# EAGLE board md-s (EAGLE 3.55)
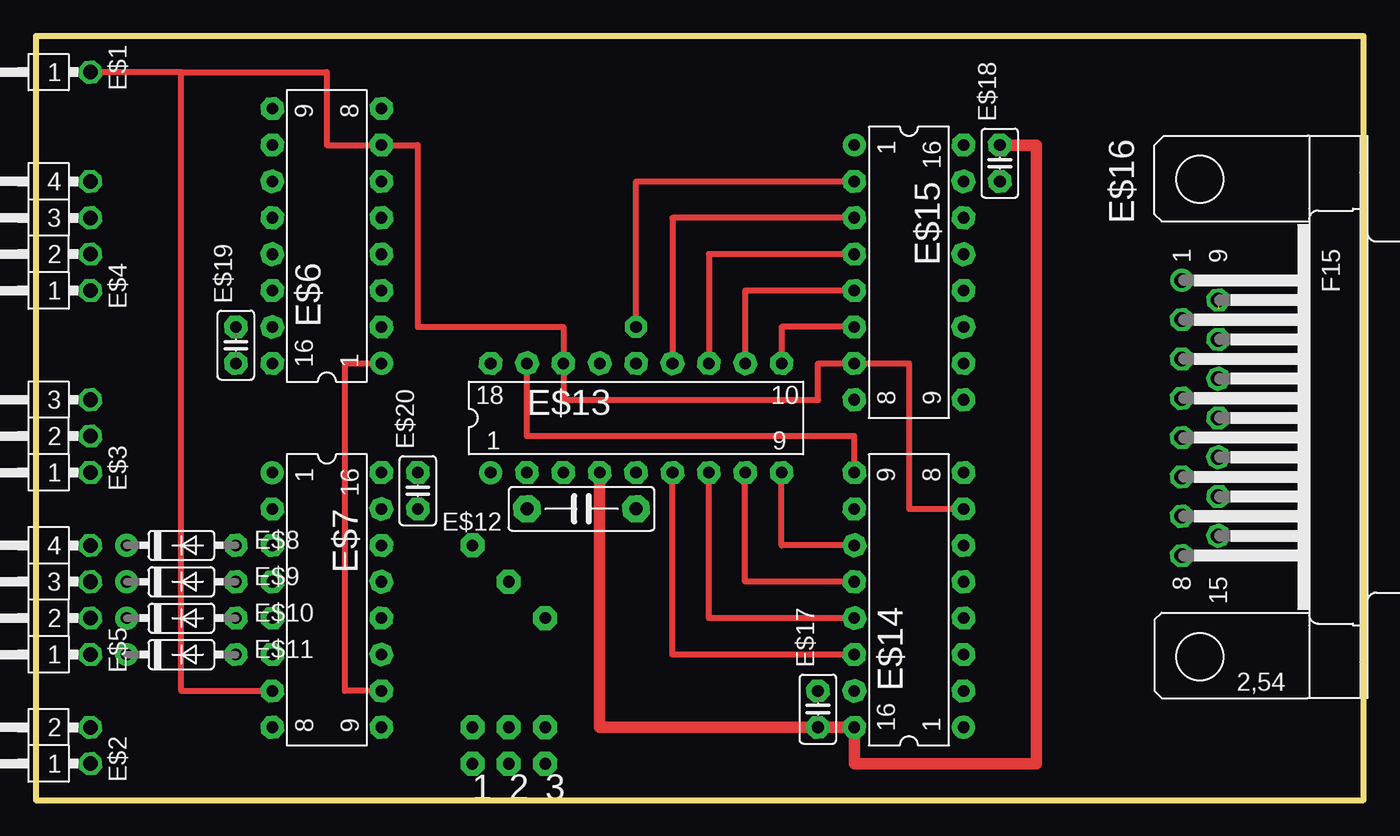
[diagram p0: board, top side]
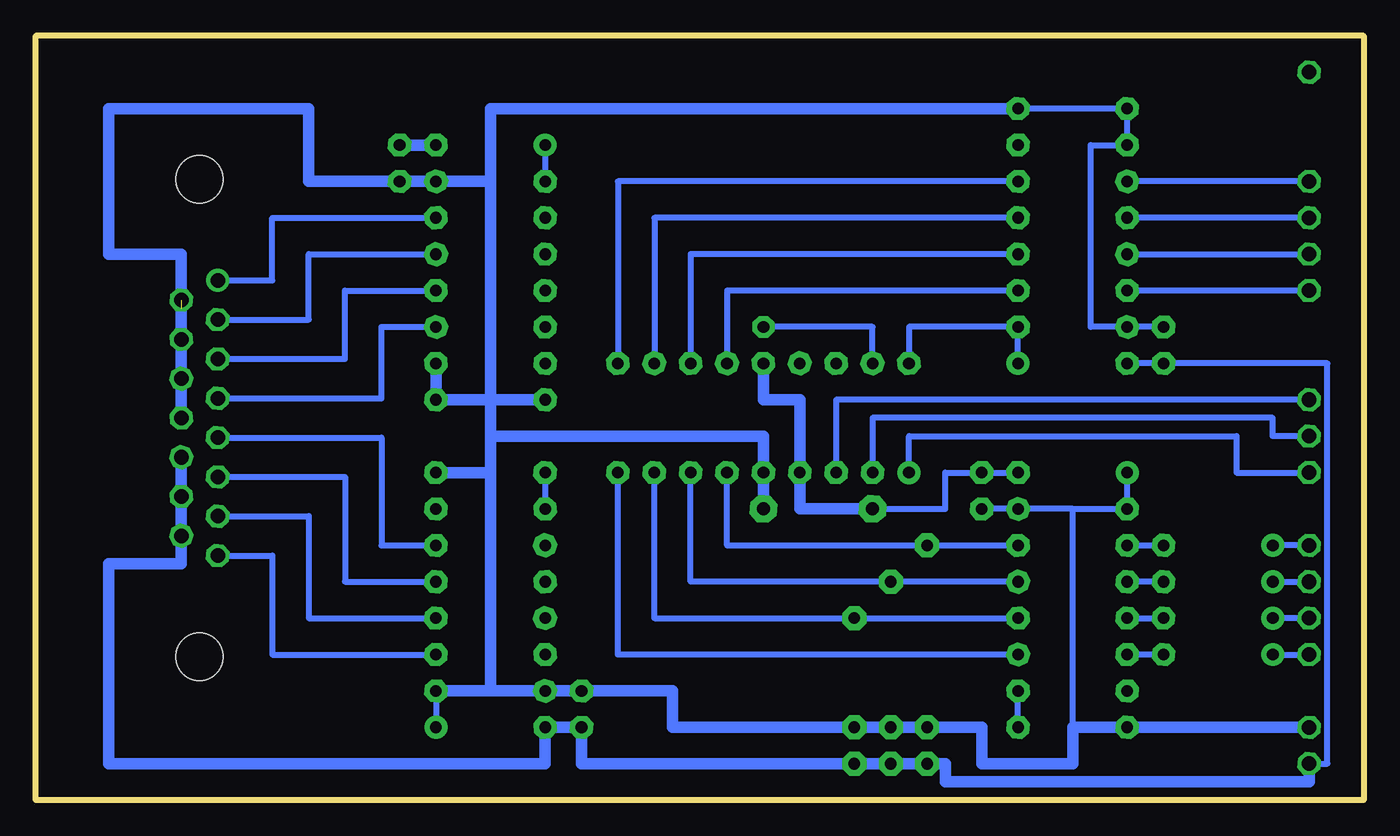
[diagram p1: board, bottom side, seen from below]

Size 92.71 x 53.34 mm. Coordinates in mm from the lower left corner, seen from the top.
Outline: 0,53.34 92.71,53.34 92.71,0 0,0 0,53.34
Copper layers used: Top, Bottom

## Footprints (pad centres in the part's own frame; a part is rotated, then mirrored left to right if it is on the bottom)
01-1W = drill 1.016 pad 1.6 octagon:  0,0
02-1W = drill 1.016 pad 1.6 octagon:  2.54,0;  0,0
03-1W = drill 1.016 pad 1.6 octagon:  5.08,0;  2.54,0;  0,0
04-1W = drill 1.016 pad 1.6 octagon:  7.62,0;  5.08,0;  2.54,0;  0,0
L16 = drill 0.813 pad 1.6 round:  -8.89,-3.81 | drill 0.813 pad 1.6 octagon:  -6.35,-3.81;  -3.81,-3.81;  -1.27,-3.81;  1.27,-3.81;  3.81,-3.81;  6.35,-3.81;  8.89,-3.81;  8.89,3.81;  6.35,3.81;  3.81,3.81;  1.27,3.81;  -1.27,3.81;  -3.81,3.81;  -6.35,3.81;  -8.89,3.81
35-7 = drill 0.813 pad 1.6 round:  -3.81,0 | drill 0.813 pad 1.6 octagon:  3.81,0
,5B3 = drill 0.914 pad 1.905 octagon:  -3.81,0;  3.81,0
L18 = drill 0.813 pad 1.6 round:  -10.16,-3.81 | drill 0.813 pad 1.6 octagon:  -7.62,-3.81;  -5.08,-3.81;  -2.54,-3.81;  0,-3.81;  2.54,-3.81;  5.08,-3.81;  7.62,-3.81;  10.16,-3.81;  10.16,3.81;  7.62,3.81;  5.08,3.81;  2.54,3.81;  0,3.81;  -2.54,3.81;  -5.08,3.81;  -7.62,3.81;  -10.16,3.81
5H = drill 1.016 pad 1.6 round:  -9.601,-1.27 | drill 1.016 pad 1.6 octagon:  -6.858,-1.27;  -4.115,-1.27;  -1.372,-1.27;  1.372,-1.27;  4.115,-1.27;  6.858,-1.27;  9.601,-1.27;  -8.23,1.27;  -5.486,1.27;  -2.743,1.27;  0,1.27;  2.743,1.27;  5.486,1.27;  8.23,1.27 | hole 3.302: -16.662,0; 16.662,0
,5-2 = drill 0.813 pad 1.6 octagon:  -1.27,0;  1.27,0

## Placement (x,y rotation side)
E$1  [01-1W]  3.81,50.8 90 top
E$2  [02-1W]  3.81,2.54 90 top
E$3  [03-1W]  3.81,22.86 90 top
E$4  [04-1W]  3.81,35.56 90 top
E$5  [04-1W]  3.81,10.16 90 top
E$6  74HC173  [L16]  20.32,39.37 90 top
E$7  74HC173  [L16]  20.32,13.97 270 top
E$8  1N4148  [35-7]  10.16,17.78 0 top
E$9  1N4148  [35-7]  10.16,15.24 0 top
E$10  1N4148  [35-7]  10.16,12.7 0 top
E$11  1N4148  [35-7]  10.16,10.16 0 top
E$12  0.1  [,5B3]  38.1,20.32 180 top
E$13  PIC16F84/10MHz  [L18]  41.91,26.67 0 top
E$14  74HC173  [L16]  60.96,13.97 90 top
E$15  74HC173  [L16]  60.96,36.83 270 top
E$16  SUB-D 15pin F  [5H]  81.28,26.67 270 top
E$17  0.1  [,5-2]  54.61,6.35 90 top
E$18  0.1  [,5-2]  67.31,44.45 90 top
E$19  0.1  [,5-2]  13.97,31.75 90 top
E$20  0.1  [,5-2]  26.67,21.59 90 top

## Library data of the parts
E$1-E$5 = con-lstb
E$6 E$7 E$14 E$15 = 74xx
E$8-E$11 = diode
E$12 E$17-E$20 = cap
E$13 = pic
E$16 = subd

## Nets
S$1: E$4. E$6.
S$2: E$4. E$6.
S$3: E$4. E$6.
S$4: E$4. E$6.
S$5: E$3. E$13.
S$6: E$3. E$13.
S$7: E$3. E$13.
S$8: E$7. E$11.
S$9: E$5. E$8.
S$10: E$5. E$9.
S$11: E$5. E$10.
S$12: E$5. E$11.
S$13: E$7. E$10.
S$14: E$7. E$9.
S$15: E$7. E$8.
S$16: E$6. E$7. E$13.
S$17: E$2. E$6. E$7. E$12. E$13. E$14. E$15. E$16. E$17. E$18. E$19. E$20.
S$18: E$7. E$13. E$14.
S$19: E$7. E$13. E$14.
S$20: E$7. E$13. E$14.
S$21: E$7. E$13. E$14.
S$22: E$2. E$6. E$7. E$12. E$13. E$14. E$15. E$16. E$17. E$18. E$19. E$20.
S$23: E$1. E$6. E$7. E$13. E$14. E$15.
S$25: E$13. E$14. E$15.
S$26: E$6. E$13. E$15.
S$27: E$6. E$13. E$15.
S$28: E$6. E$13. E$15.
S$29: E$6. E$13. E$15.
S$32: E$14. E$16.
S$33: E$14. E$16.
S$34: E$14. E$16.
S$35: E$14. E$16.
S$36: E$15. E$16.
S$37: E$15. E$16.
S$38: E$15. E$16.
S$39: E$15. E$16.

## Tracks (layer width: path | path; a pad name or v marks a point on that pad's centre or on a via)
S$1
  Bottom 0.406: 3.81,43.18 16.51,43.18
S$2
  Bottom 0.406: 3.81,40.64 16.51,40.64
S$3
  Bottom 0.406: 16.51,38.1 3.81,38.1
S$4
  Bottom 0.406: E$4. 16.51,35.56
S$5
  Bottom 0.406: 3.81,27.94 36.83,27.94 36.83,22.86
S$6
  Bottom 0.406: 3.81,25.4 6.35,25.4 6.35,26.67 34.29,26.67 34.29,22.86
S$7
  Bottom 0.406: 31.75,22.86 31.75,25.4 8.89,25.4 8.89,22.86 E$3.
S$8
  Bottom 0.406: E$11. 16.51,10.16
S$9
  Bottom 0.406: 3.81,17.78 6.35,17.78
S$10
  Bottom 0.406: 6.35,15.24 3.81,15.24
S$11
  Bottom 0.406: 3.81,12.7 6.35,12.7
S$12
  Bottom 0.406: 6.35,10.16 E$5.
S$13
  Bottom 0.406: 16.51,12.7 E$10.
S$14
  Bottom 0.406: E$9. 16.51,15.24
S$15
  Bottom 0.406: 16.51,17.78 E$8.
S$16
  Top 0.406: 24.13,7.62 21.59,7.62 21.59,30.48 24.13,30.48
  Bottom 0.406: 24.13,5.08 24.13,7.62 | 24.13,30.48 24.13,33.02 31.75,33.02 E$13.
S$17  (via drill 0.81 pad 1.68)  (1 unrouted)
  Bottom 0.406: 64.77,7.62 64.77,5.08 | 24.13,48.26 16.51,48.26 16.51,45.72 19.05,45.72 19.05,33.02 16.51,33.02 E$19. | 26.67,20.32 24.13,20.32 20.32,20.32 | 16.51,22.86 16.51,20.32 20.32,20.32 | 20.32,5.08 20.32,20.32
  Bottom 0.813: 82.55,26.67 82.55,29.41 82.55,32.16 82.55,34.29 | 82.55,34.9 82.55,38.1 87.63,38.1 87.63,48.26 73.66,48.26 73.66,43.18 67.31,43.18 64.77,43.18 60.96,43.18 | 41.91,20.32 41.91,22.86 41.91,25.4 60.96,25.4 | 60.96,7.62 64.77,7.62 | 60.96,7.62 57.15,7.62 E$17. 48.26,7.62 48.26,5.08 v35.56,5.08 v33.02,5.08 v30.48,5.08 26.67,5.08 26.67,2.54 20.32,2.54 20.32,5.08 16.51,5.08 3.81,5.08 | 60.96,22.86 64.77,22.86 | 60.96,22.86 60.96,7.62 | 60.96,25.4 60.96,22.86 | 64.77,30.48 64.77,27.94 60.96,27.94 | 60.96,27.94 57.15,27.94 | 60.96,27.94 60.96,25.4 | 60.96,43.18 60.96,27.94 | 60.96,43.18 60.96,48.26 24.13,48.26
S$18
  Top 0.406: 57.15,17.78 52.07,17.78 52.07,22.86
  Bottom 0.406: 52.07,22.86 52.07,10.16 24.13,10.16
S$19  (via drill 0.81 pad 1.68)
  Top 0.406: 57.15,15.24 49.53,15.24 49.53,22.86
  Bottom 0.406: 49.53,22.86 49.53,12.7 v35.56,12.7 24.13,12.7
S$20  (via drill 0.81 pad 1.68)
  Top 0.406: 57.15,12.7 46.99,12.7 46.99,22.86
  Bottom 0.406: 46.99,22.86 46.99,15.24 v33.02,15.24 24.13,15.24
S$21  (via drill 0.81 pad 1.68)
  Top 0.406: 57.15,10.16 44.45,10.16 44.45,22.86
  Bottom 0.406: 44.45,22.86 44.45,17.78 v30.48,17.78 24.13,17.78
S$22  (via drill 0.81 pad 1.68)
  Top 0.813: E$18. 69.85,45.72 69.85,2.54 57.15,2.54 E$14. 54.61,5.08 39.37,5.08 39.37,22.86
  Bottom 0.406: E$7. E$20. 29.21,22.86 29.21,20.32 E$12. | E$6. 13.97,30.48 2.54,30.48 2.54,2.54 E$2.
  Bottom 0.813: 82.55,21.59 82.55,23.93 | 82.55,21.59 82.55,21.18 | 82.55,21.59 E$16. 82.55,16.51 87.63,16.51 87.63,2.54 57.15,2.54 E$14. 54.61,5.08 54.61,2.54 v35.56,2.54 v33.02,2.54 v30.48,2.54 29.21,2.54 29.21,1.27 3.81,1.27 E$2. | E$18. E$15. | 41.91,30.48 41.91,27.94 39.37,27.94 39.37,22.86 39.37,20.32 E$12.
S$23
  Top 0.406: 10.16,50.8 E$1. | 10.16,50.8 20.32,50.8 20.32,45.72 24.13,45.72 26.67,45.72 26.67,33.02 36.83,33.02 36.83,30.48 36.83,27.94 54.61,27.94 54.61,30.48 57.15,30.48 60.96,30.48 60.96,20.32 64.77,20.32 | 16.51,7.62 10.16,7.62 10.16,50.8
S$25  (via drill 0.81 pad 1.52)
  Top 0.406: v41.91,33.02 41.91,43.18 57.15,43.18 | 57.15,22.86 57.15,25.4 34.29,25.4 34.29,30.48
  Bottom 0.406: 34.29,30.48 34.29,33.02 v41.91,33.02 | 57.15,45.72 57.15,43.18 | 57.15,22.86 57.15,20.32
S$26
  Top 0.406: 57.15,40.64 44.45,40.64 44.45,30.48
  Bottom 0.406: 24.13,35.56 44.45,35.56 44.45,30.48
S$27
  Top 0.406: 57.15,38.1 46.99,38.1 46.99,30.48
  Bottom 0.406: 24.13,38.1 46.99,38.1 46.99,30.48
S$28
  Top 0.406: 57.15,35.56 49.53,35.56 49.53,30.48
  Bottom 0.406: 24.13,40.64 49.53,40.64 49.53,30.48
S$29
  Top 0.406: 57.15,33.02 52.07,33.02 52.07,30.48
  Bottom 0.406: 24.13,43.18 52.07,43.18 52.07,30.48
S$32
  Bottom 0.406: 80.01,17.07 76.2,17.07 76.2,10.16 64.77,10.16
S$33
  Bottom 0.406: 80.01,19.81 73.66,19.81 73.66,12.7 64.77,12.7
S$34
  Bottom 0.406: 80.01,22.55 71.12,22.55 71.12,15.24 64.77,15.24
S$35
  Bottom 0.406: 80.01,25.3 68.58,25.3 68.58,17.78 64.77,17.78
S$36
  Bottom 0.406: 80.01,28.04 68.58,28.04 68.58,33.02 64.77,33.02
S$37
  Bottom 0.406: 80.01,30.78 71.12,30.78 71.12,35.56 64.77,35.56
S$38
  Bottom 0.406: 80.01,33.53 73.66,33.53 73.66,38.1 64.77,38.1
S$39
  Bottom 0.406: 80.01,36.27 76.2,36.27 76.2,40.64 64.77,40.64

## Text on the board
tPlace: 1 | 2 | 3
